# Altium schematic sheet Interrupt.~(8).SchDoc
size A; SheetNumber: 1; SheetTotal: 1
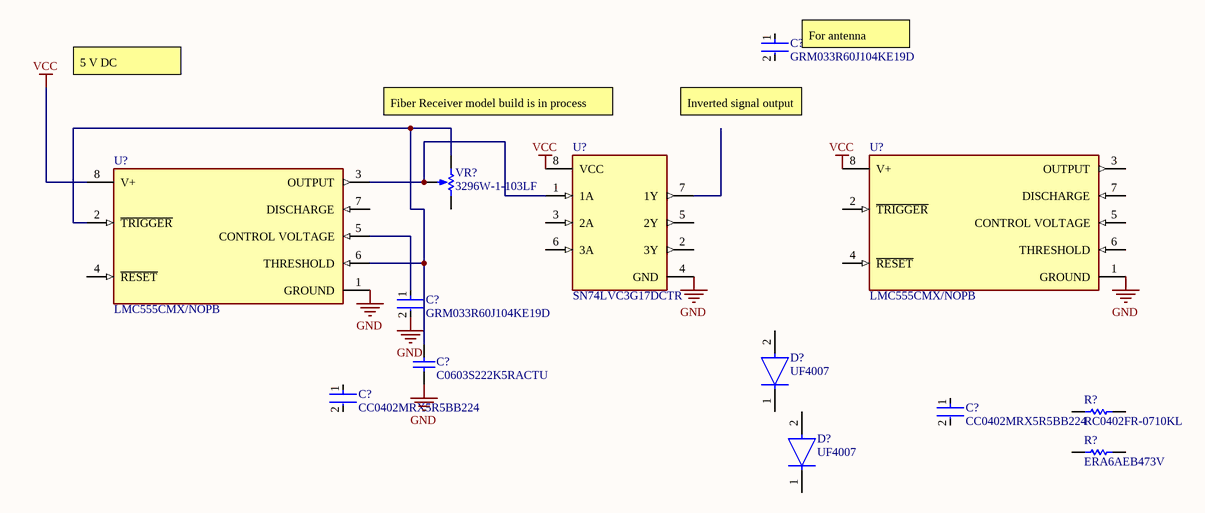
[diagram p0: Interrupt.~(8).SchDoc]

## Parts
(Parts that share a designator on the sheet are numbered #1, #2 ... from top to bottom, then left to right.)
C?#1  GRM033R60J104KE19D  [FP-GRM033-0_03-MFG]
C?#2  GRM033R60J104KE19D  [FP-GRM033-0_03-MFG]
C?#3  C0603S222K5RACTU  [CAPC1608X87X35NL15T15]
C?#4  CC0402MRX5R5BB224  [FP-CC0402-MFG]
C?#5  CC0402MRX5R5BB224  [FP-CC0402-MFG]
D?#1  UF4007  [FP-017AH-MFG]
D?#2  UF4007  [FP-017AH-MFG]
R?#1  RC0402FR-0710KL  [RESC1005X40X25LL05T10]
R?#2  ERA6AEB473V  [RESC2013X60X40LL20T25]
U?#1  SN74LVC3G17DCTR  [FP-DCT0008A-MFG]
U?#2  LMC555CMX/NOPB  [FP-D0008A-MFG]
U?#3  LMC555CMX/NOPB  [FP-D0008A-MFG]
VR?  3296W-1-103LF  [BOUR-3296W]

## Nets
GND: C?#2.2 C?#3.1 U?#1.4(GND) U?#2.1(GROUND) U?#3.1(GROUND)
VCC: U?#1.8(VCC) U?#2.8(V+) U?#3.8(V+)
NetC?#2_1: C?#2.1 U?#3.5(CONTROL_VOLTAGE)
NetC?#3_2: C?#3.2 U?#3.2(~{TRIGGER}) U?#3.6(THRESHOLD) VR?.1(CCW)
NetU?#1_1: U?#1.1(1A) U?#3.3(OUTPUT) VR?.2(S)

Not connected (* = marked no-connect by the designer): C?#1 1 2; C?#4 1 2; C?#5 1 2; D?#1 1(C) 2(A); D?#2 1(C) 2(A); R?#1 1 2; R?#2 1 2; U?#1 2(3Y) 3(2A) 5(2Y) 6(3A) 7(1Y); U?#2 2(~{TRIGGER}) 3(OUTPUT) 4(~{RESET}) 5(CONTROL_VOLTAGE) 6(THRESHOLD) 7(DISCHARGE); U?#3 4(~{RESET}) 7(DISCHARGE); VR? 3(CW)

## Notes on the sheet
- 5 V DC
- (near C?#1) For antenna
- Fiber Receiver model build is in process
- Inverted signal output

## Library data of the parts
C?#1 = CMP-06035-000062-2: Chip Multilayer Ceramic Capacitors for General Purpose, 0201, 0.10uF, X5R, 15%, 10%, 6.3V; Capacitance: 100nF
C?#2 = CMP-06035-000062-2: 100 nF Chip Multilayer Ceramic Capacitors for General Purpose, 0201, 0.10uF, X5R, 15%, 10%, 6.3V; Capacitance: 100nF
C?#3 = CMP-2006-03289-1: Manufacturer: Kemet
C?#4 C?#5 = CMP-03422-000657-1: CAP CER 0.22UF 6.3V X5R 0402; Manufacturer: YAGEO; Automotive Grade: NA; Material: Ceramic; Value: 220 nF; Tolerance: 0.2; Temperature Coefficient: 30ppm/°C
D?#1 D?#2 = CMP-2000-05028-2: DIODE GEN PURP 1KV 1A DO41; Manufacturer: ON Semiconductor; Capacitance: 17pF; Max Surge Forward Current: 30A; Max Repetitive Reverse Voltage: 1000V; Value: 17pF; Max Junction Temp: +150°C; Peak Reverse Current: 10uA
R?#1 = CMP-2002-07353-1: Manufacturer: Yageo / Phycomp
R?#2 = CMP-2001-00645-1: Manufacturer: Panasonic
U?#1 = CMP-0859-00525-5: IC BUFFER NON-INVERT 5.5V SM8; Manufacturer: Texas Instruments; Logic Function Desc: Non-Inverting; Propagation Delay: 5.1ns; Number Of Inputs: 3; Standoff Height: 0mm; Nominal Supply Current: 10uA; Min Supply Voltage: 1.65V
U?#2 U?#3 = CMP-04858-000001-1: IC OSC SINGLE TIMER 3MHZ 8-SOIC; Manufacturer: Texas Instruments; Number Of Timers/Counters: 1; Max Supply Voltage: 15V; Standoff Height: 0.11mm; Propagation Delay: 100ns; Nominal Supply Current: 50-150uA; Min Supply Voltage: 1.5V
VR? = CMP-1747-00001-1: Square Trimpot(R) Trimming Potentiometer, 10 KOhm, +/- 10%, 0.5 W, -55 to 125 degC, 3-Pin THD, RoHS, Tube; Voltage Rating: 75 V; Resistance: 120 Ohm; Tolerance: 1%; Power Rating: 100 mW; Case\Package: 0603; Type (Resistor): Thick Film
